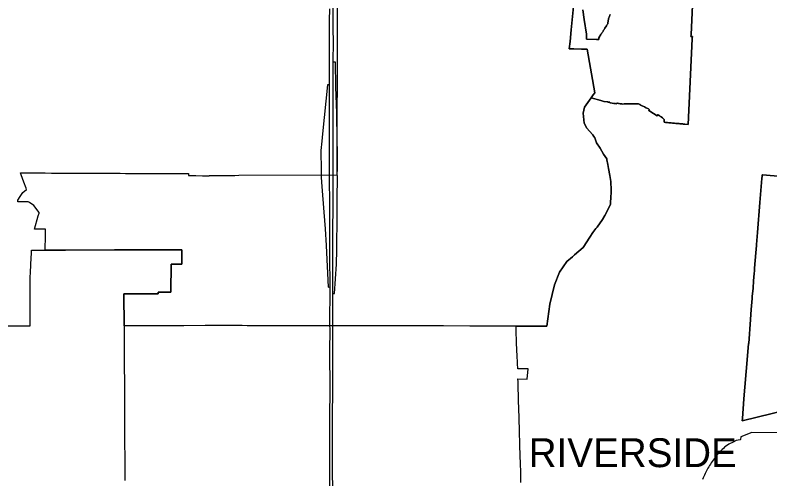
# Model space of a CAD drawing. Extents: x 0 to 34, y 0 to 22.
# Drawn here: x 5.231 to 5.4412, y 15.5644 to 15.6936 of the extents above; entities that cross this region are included whole.
import ezdxf

# ---------------------------------------------------------------- set-up
doc = ezdxf.new("R2010")
doc.units = 0
for name, color, linetype in [('GM_X_Corporation', 7, 'Continuous'), ('GM_X_Corporation_Text', 7, 'Continuous'), ('GM_X_Interchange_Ramps', 7, 'Continuous'), ('GM_X_Interstate_Route', 7, 'Continuous')]:
    doc.layers.add(name, color=color, linetype=linetype)

msp = doc.modelspace()

# ---------------------------------------------------------------- linework, layer by layer
at = {"layer": 'GM_X_Corporation'}
for points in [[(5.38669, 15.69795), (5.38613, 15.69231), (5.38584, 15.68951), (5.38552, 15.68626), (5.38531, 15.68419), (5.38658, 15.68417), (5.38662, 15.68417), (5.38872, 15.68415), (5.38967, 15.68413), (5.39032, 15.68413), (5.3924, 15.67197), (5.39196, 15.67136), (5.39136, 15.67053), (5.38951, 15.66794), (5.38918, 15.66628), (5.38944, 15.66353), (5.38997, 15.6625), (5.39011, 15.66222), (5.39185, 15.66023), (5.39215, 15.65979), (5.3924, 15.65943), (5.39277, 15.65832), (5.39281, 15.65818), (5.39292, 15.65801), (5.39389, 15.65652), (5.3948, 15.65487), (5.39572, 15.65354), (5.39578, 15.65324), (5.39602, 15.65198), (5.39623, 15.65087), (5.3966, 15.64894), (5.39687, 15.64725), (5.39699, 15.64486), (5.39684, 15.64223), (5.39682, 15.64195), (5.39675, 15.64086), (5.39624, 15.63982), (5.39528, 15.63785), (5.39521, 15.63774), (5.39457, 15.63664), (5.39305, 15.63457), (5.39273, 15.63414), (5.3919, 15.633), (5.39099, 15.63177), (5.38917, 15.62886), (5.38678, 15.62679), (5.38618, 15.62627), (5.38467, 15.62497), (5.38261, 15.62195), (5.38121, 15.61847), (5.37994, 15.61307), (5.37908, 15.60694), (5.37819, 15.60694), (5.37797, 15.60694), (5.37758, 15.60694), (5.37715, 15.60694), (5.37697, 15.60695), (5.37468, 15.60695), (5.37461, 15.60695), (5.3742, 15.60695), (5.37215, 15.60695), (5.37047, 15.60695), (5.37006, 15.60695), (5.36442, 15.60696), (5.36409, 15.60696), (5.36375, 15.60696), (5.36347, 15.60696), (5.36334, 15.60696), (5.36305, 15.60696), (5.36272, 15.60697), (5.36039, 15.60698), (5.3603, 15.60698), (5.35998, 15.60698), (5.35764, 15.60699), (5.35032, 15.60702), (5.34996, 15.60702), (5.34984, 15.60703), (5.34662, 15.60703), (5.34509, 15.60703), (5.345, 15.60703), (5.34161, 15.60704), (5.34085, 15.60704), (5.33591, 15.60705), (5.33419, 15.60705), (5.33385, 15.60705), (5.33353, 15.60705), (5.33123, 15.60705), (5.3283, 15.60706), (5.32801, 15.60706), (5.32687, 15.60706), (5.32654, 15.60706), (5.32596, 15.60706), (5.32534, 15.60706), (5.32339, 15.60707), (5.32133, 15.60707), (5.32062, 15.60707), (5.32049, 15.60707), (5.32039, 15.60707), (5.31939, 15.60707), (5.31862, 15.60707), (5.31754, 15.60708), (5.312, 15.60709), (5.31032, 15.60709), (5.30879, 15.60709), (5.30866, 15.60709), (5.308, 15.60709), (5.30621, 15.60708), (5.30559, 15.60708), (5.30476, 15.60708), (5.3043, 15.60708), (5.30115, 15.60706), (5.30111, 15.60706), (5.29839, 15.60708), (5.29802, 15.60708), (5.29787, 15.60709), (5.2976, 15.60709), (5.29737, 15.60709), (5.29561, 15.60709), (5.29421, 15.6071), (5.29231, 15.6071), (5.29135, 15.6071), (5.29035, 15.60711), (5.29032, 15.60711), (5.29012, 15.60711), (5.28775, 15.60711), (5.28743, 15.60711), (5.28621, 15.60712), (5.2859, 15.60712), (5.28569, 15.60712), (5.28553, 15.60712), (5.2855, 15.60712), (5.28504, 15.60712), (5.28394, 15.60712), (5.27803, 15.60709), (5.2775, 15.60709), (5.27749, 15.60709), (5.27546, 15.60708), (5.2745, 15.60708), (5.27355, 15.60708), (5.26139, 15.60706), (5.26139, 15.60713), (5.26138, 15.60812), (5.26137, 15.60919), (5.26136, 15.61032), (5.26133, 15.61258), (5.2613, 15.61548), (5.26129, 15.61584), (5.26129, 15.61593), (5.26828, 15.61593), (5.27083, 15.61593), (5.27083, 15.61597), (5.27084, 15.61642), (5.27442, 15.61642), (5.27442, 15.61648), (5.27449, 15.62421), (5.27449, 15.62422), (5.27709, 15.6242), (5.27741, 15.62419), (5.27743, 15.62537), (5.27743, 15.6254), (5.27745, 15.6282), (5.26348, 15.6282), (5.2617, 15.6282), (5.25869, 15.6282), (5.24508, 15.62813), (5.24355, 15.62813), (5.24329, 15.62813), (5.24205, 15.62813), (5.24181, 15.62813), (5.24084, 15.62813), (5.23942, 15.62813), (5.23943, 15.62943), (5.23946, 15.63087), (5.23946, 15.63174), (5.23945, 15.63398), (5.23792, 15.63398), (5.2364, 15.63398), (5.23749, 15.63771), (5.2377, 15.63843), (5.23776, 15.63863), (5.23626, 15.64056), (5.23502, 15.64137), (5.2347, 15.64158), (5.23463, 15.64158), (5.2325, 15.64159), (5.23192, 15.64159), (5.23181, 15.64159), (5.23181, 15.64192), (5.23181, 15.64208), (5.23244, 15.64305), (5.2332, 15.64421), (5.23421, 15.64502), (5.23407, 15.64542), (5.23346, 15.64708), (5.23271, 15.64914), (5.23253, 15.64963), (5.2336, 15.64964), (5.23364, 15.64964), (5.23373, 15.64964), (5.23569, 15.64963), (5.23697, 15.64963), (5.23795, 15.64962), (5.2394, 15.64962), (5.24114, 15.64961), (5.24299, 15.6496), (5.24352, 15.6496), (5.24555, 15.64959), (5.2471, 15.64958), (5.24795, 15.64958), (5.24864, 15.64958), (5.25018, 15.64957), (5.25174, 15.64956), (5.25254, 15.64956), (5.25407, 15.64955), (5.25527, 15.64955), (5.25562, 15.64955), (5.25716, 15.64954), (5.2587, 15.64953), (5.25901, 15.64953), (5.26025, 15.64953), (5.26179, 15.64952), (5.26333, 15.64951), (5.26366, 15.64951), (5.26488, 15.64951), (5.26642, 15.6495), (5.26796, 15.6495), (5.27194, 15.64948), (5.27827, 15.64945), (5.27929, 15.64943), (5.27928, 15.64888), (5.28062, 15.64888), (5.28136, 15.64888), (5.2832, 15.64887), (5.28506, 15.64886), (5.28506, 15.64895), (5.28585, 15.64895), (5.28744, 15.64895), (5.28903, 15.64896), (5.28951, 15.64896), (5.28988, 15.64896), (5.28991, 15.64896), (5.29073, 15.64896), (5.29158, 15.64896), (5.29221, 15.64896), (5.29328, 15.64897), (5.32068, 15.64911), (5.32068, 15.64931), (5.32068, 15.64951), (5.32076, 15.69174), (5.32069, 15.70479)], [(5.37185, 15.56337), (5.37178, 15.56615), (5.3717, 15.56879), (5.37169, 15.56932), (5.37166, 15.57019), (5.37154, 15.57451), (5.37146, 15.57712), (5.37142, 15.57873), (5.37137, 15.58034), (5.37137, 15.58036), (5.37134, 15.58135), (5.37134, 15.58159), (5.37132, 15.58217), (5.37129, 15.58317), (5.37128, 15.58344), (5.37128, 15.58357), (5.37127, 15.58399), (5.37126, 15.58437), (5.37122, 15.58583), (5.37106, 15.59144), (5.37103, 15.59224), (5.3736, 15.59223), (5.37382, 15.59506), (5.37357, 15.59506), (5.37095, 15.59505), (5.37095, 15.59514), (5.37089, 15.5965), (5.37087, 15.59699), (5.37081, 15.5985), (5.37081, 15.59861), (5.37066, 15.60222), (5.37064, 15.60269), (5.3706, 15.60374), (5.37057, 15.60443), (5.37048, 15.60667), (5.37047, 15.60695), (5.37215, 15.60695), (5.37461, 15.60695), (5.37468, 15.60695), (5.37697, 15.60695), (5.37715, 15.60694), (5.37758, 15.60694), (5.37797, 15.60694), (5.37819, 15.60694), (5.37908, 15.60694), (5.37994, 15.61307), (5.38121, 15.61847), (5.38261, 15.62195), (5.38467, 15.62497), (5.38618, 15.62627), (5.38678, 15.62679), (5.38917, 15.62886), (5.39099, 15.63177), (5.3919, 15.633), (5.39273, 15.63414), (5.39305, 15.63457), (5.39457, 15.63664), (5.39521, 15.63774), (5.39528, 15.63785), (5.39624, 15.63982), (5.39675, 15.64086), (5.39682, 15.64195), (5.39684, 15.64223), (5.39699, 15.64486), (5.39687, 15.64725), (5.3966, 15.64894), (5.39623, 15.65087), (5.39602, 15.65198), (5.39578, 15.65324), (5.39572, 15.65354), (5.3948, 15.65487), (5.39389, 15.65652), (5.39292, 15.65801), (5.39281, 15.65818), (5.39277, 15.65832), (5.3924, 15.65943), (5.39215, 15.65979), (5.39185, 15.66023), (5.39011, 15.66222), (5.38997, 15.6625), (5.38944, 15.66353), (5.38918, 15.66628), (5.38951, 15.66794), (5.39136, 15.67053), (5.39407, 15.6698), (5.3949, 15.66957), (5.39506, 15.66953), (5.39588, 15.66941), (5.39607, 15.66939), (5.39612, 15.66938), (5.39631, 15.66936), (5.39643, 15.66934), (5.3966, 15.66932), (5.39658, 15.66916), (5.39665, 15.66915), (5.39678, 15.66913), (5.39725, 15.66906), (5.39773, 15.669), (5.39821, 15.66893), (5.39849, 15.6689), (5.39851, 15.66905), (5.3987, 15.66903), (5.39899, 15.66899), (5.39918, 15.66896), (5.39947, 15.66892), (5.39966, 15.6689), (5.39994, 15.66886), (5.40013, 15.66883), (5.40055, 15.66884), (5.40074, 15.66885), (5.40103, 15.66885), (5.40122, 15.66886), (5.40152, 15.66886), (5.4017, 15.66887), (5.402, 15.66887), (5.40219, 15.66888), (5.40248, 15.66888), (5.40267, 15.66889), (5.40296, 15.66889), (5.40315, 15.6689), (5.40344, 15.6689), (5.40363, 15.66891), (5.40393, 15.66891), (5.40411, 15.66892), (5.40438, 15.66892), (5.40446, 15.66892), (5.40456, 15.66887), (5.40479, 15.66875), (5.40494, 15.66867), (5.40522, 15.66853), (5.40537, 15.66845), (5.40564, 15.66831), (5.4058, 15.66823), (5.40607, 15.66809), (5.40622, 15.66801), (5.4065, 15.66787), (5.40665, 15.66779), (5.40672, 15.66776), (5.40687, 15.66768), (5.40714, 15.66754), (5.40734, 15.66744), (5.40757, 15.66731), (5.40742, 15.66703), (5.40878, 15.6662), (5.40982, 15.66556), (5.41007, 15.66587), (5.4101, 15.66585), (5.41045, 15.66557), (5.41048, 15.66555), (5.41083, 15.66528), (5.41086, 15.66525), (5.41124, 15.66495), (5.41154, 15.66472), (5.41176, 15.66455), (5.41176, 15.66452), (5.41172, 15.66374), (5.4121, 15.66371), (5.4122, 15.6637), (5.41258, 15.66366), (5.41268, 15.66365), (5.41306, 15.66362), (5.41316, 15.66361), (5.41354, 15.66358), (5.41364, 15.66357), (5.41402, 15.66353), (5.41412, 15.66352), (5.4145, 15.66349), (5.4146, 15.66348), (5.41498, 15.66344), (5.41508, 15.66343), (5.41546, 15.6634), (5.41556, 15.66339), (5.41594, 15.66336), (5.41605, 15.66335), (5.41642, 15.66331), (5.41653, 15.6633), (5.4169, 15.66327), (5.41701, 15.66326), (5.41746, 15.66322), (5.41749, 15.66321), (5.41842, 15.66313), (5.41955, 15.68699), (5.41956, 15.68706), (5.41956, 15.68715), (5.41958, 15.68763), (5.41917, 15.68767), (5.41917, 15.68767), (5.4192, 15.68816), (5.4197, 15.69842)], [(5.4197, 15.69842), (5.4192, 15.68816), (5.41917, 15.68767), (5.41917, 15.68767), (5.41958, 15.68763), (5.41956, 15.68715), (5.41956, 15.68706), (5.41955, 15.68699), (5.41842, 15.66313), (5.41749, 15.66321), (5.41746, 15.66322), (5.41701, 15.66326), (5.4169, 15.66327), (5.41653, 15.6633), (5.41642, 15.66331), (5.41605, 15.66335), (5.41594, 15.66336), (5.41556, 15.66339), (5.41546, 15.6634), (5.41508, 15.66343), (5.41498, 15.66344), (5.4146, 15.66348), (5.4145, 15.66349), (5.41412, 15.66352), (5.41402, 15.66353), (5.41364, 15.66357), (5.41354, 15.66358), (5.41316, 15.66361), (5.41306, 15.66362), (5.41268, 15.66365), (5.41258, 15.66366), (5.4122, 15.6637), (5.4121, 15.66371), (5.41172, 15.66374), (5.41176, 15.66452), (5.41176, 15.66455), (5.41154, 15.66472), (5.41124, 15.66495), (5.41086, 15.66525), (5.41083, 15.66528), (5.41048, 15.66555), (5.41045, 15.66557), (5.4101, 15.66585), (5.41007, 15.66587), (5.40982, 15.66556), (5.40878, 15.6662), (5.40742, 15.66703), (5.40757, 15.66731), (5.40734, 15.66744), (5.40714, 15.66754), (5.40687, 15.66768), (5.40672, 15.66776), (5.40665, 15.66779), (5.4065, 15.66787), (5.40622, 15.66801), (5.40607, 15.66809), (5.4058, 15.66823), (5.40564, 15.66831), (5.40537, 15.66845), (5.40522, 15.66853), (5.40494, 15.66867), (5.40479, 15.66875), (5.40456, 15.66887), (5.40446, 15.66892), (5.40438, 15.66892), (5.40411, 15.66892), (5.40393, 15.66891), (5.40363, 15.66891), (5.40344, 15.6689), (5.40315, 15.6689), (5.40296, 15.66889), (5.40267, 15.66889), (5.40248, 15.66888), (5.40219, 15.66888), (5.402, 15.66887), (5.4017, 15.66887), (5.40152, 15.66886), (5.40122, 15.66886), (5.40103, 15.66885), (5.40074, 15.66885), (5.40055, 15.66884), (5.40013, 15.66883), (5.39994, 15.66886), (5.39966, 15.6689), (5.39947, 15.66892), (5.39918, 15.66896), (5.39899, 15.66899), (5.3987, 15.66903), (5.39851, 15.66905), (5.39849, 15.6689), (5.39821, 15.66893), (5.39773, 15.669), (5.39725, 15.66906), (5.39678, 15.66913), (5.39665, 15.66915), (5.39658, 15.66916), (5.3966, 15.66932), (5.39643, 15.66934), (5.39631, 15.66936), (5.39612, 15.66938), (5.39607, 15.66939), (5.39588, 15.66941), (5.39506, 15.66953), (5.3949, 15.66957), (5.39407, 15.6698), (5.39136, 15.67053), (5.39196, 15.67136), (5.3924, 15.67197), (5.39032, 15.68413), (5.38967, 15.68413), (5.38872, 15.68415), (5.38662, 15.68417), (5.38658, 15.68417), (5.38531, 15.68419), (5.38552, 15.68626), (5.38584, 15.68951), (5.38613, 15.69231), (5.38669, 15.69795)], [(5.38907, 15.69508), (5.38944, 15.69233), (5.39008, 15.68827), (5.39015, 15.68692), (5.39287, 15.68681), (5.3932, 15.68679), (5.39325, 15.68679), (5.39342, 15.68679), (5.39355, 15.68678), (5.39353, 15.68703), (5.39352, 15.68716), (5.39351, 15.68724), (5.39383, 15.68774), (5.3939, 15.68785), (5.39395, 15.68792), (5.39409, 15.68815), (5.3942, 15.68833), (5.39435, 15.68856), (5.39446, 15.68873), (5.39461, 15.68897), (5.39472, 15.68914), (5.39487, 15.68937), (5.39498, 15.68955), (5.39513, 15.68978), (5.39524, 15.68996), (5.39539, 15.69019), (5.3955, 15.69037), (5.39564, 15.69059), (5.39576, 15.69078), (5.3959, 15.691), (5.396, 15.69115), (5.396, 15.69118), (5.39607, 15.69155), (5.39611, 15.6918), (5.39615, 15.69205), (5.3962, 15.69233), (5.39623, 15.69254), (5.39628, 15.69281), (5.3963, 15.69285), (5.39637, 15.69301), (5.39651, 15.6933), (5.39658, 15.69345), (5.39671, 15.69373)], [(5.39671, 15.69373), (5.39658, 15.69345), (5.39651, 15.6933), (5.39637, 15.69301), (5.3963, 15.69285), (5.39628, 15.69281), (5.39623, 15.69254), (5.3962, 15.69233), (5.39615, 15.69205), (5.39611, 15.6918), (5.39607, 15.69155), (5.396, 15.69118), (5.396, 15.69115), (5.3959, 15.691), (5.39576, 15.69078), (5.39564, 15.69059), (5.3955, 15.69037), (5.39539, 15.69019), (5.39524, 15.68996), (5.39513, 15.68978), (5.39498, 15.68955), (5.39487, 15.68937), (5.39472, 15.68914), (5.39461, 15.68897), (5.39446, 15.68873), (5.39435, 15.68856), (5.3942, 15.68833), (5.39409, 15.68815), (5.39395, 15.68792), (5.3939, 15.68785), (5.39383, 15.68774), (5.39351, 15.68724), (5.39352, 15.68716), (5.39353, 15.68703), (5.39355, 15.68678), (5.39342, 15.68679), (5.39325, 15.68679), (5.3932, 15.68679), (5.39287, 15.68681), (5.39015, 15.68692), (5.39008, 15.68827), (5.38944, 15.69233), (5.38944, 15.69235), (5.38907, 15.69508)], [(5.45847, 15.58674), (5.43344, 15.58058), (5.43349, 15.58122), (5.43393, 15.58667), (5.43481, 15.59761), (5.43525, 15.60208), (5.43526, 15.60216), (5.43575, 15.60878), (5.43598, 15.61164), (5.43614, 15.61362), (5.43616, 15.61396), (5.43621, 15.61449), (5.43623, 15.61475), (5.43627, 15.61522), (5.43646, 15.61754), (5.43662, 15.6196), (5.43679, 15.62162), (5.43685, 15.62235), (5.43689, 15.6229), (5.43691, 15.62308), (5.43726, 15.62736), (5.43743, 15.62943), (5.43745, 15.62972), (5.43772, 15.63301), (5.4384, 15.64136), (5.43895, 15.64807), (5.43895, 15.64815), (5.43899, 15.64863), (5.43903, 15.64912), (5.43915, 15.64911), (5.4573, 15.64753)], [(5.4573, 15.64753), (5.43915, 15.64911), (5.43903, 15.64912), (5.43899, 15.64863), (5.43895, 15.64815), (5.43895, 15.64807), (5.4384, 15.64136), (5.43772, 15.63301), (5.43745, 15.62972), (5.43743, 15.62943), (5.43726, 15.62736), (5.43691, 15.62308), (5.43689, 15.6229), (5.43685, 15.62235), (5.43679, 15.62162), (5.43662, 15.6196), (5.43646, 15.61754), (5.43627, 15.61522), (5.43623, 15.61475), (5.43621, 15.61449), (5.4362, 15.61442), (5.43616, 15.61396), (5.43614, 15.61362), (5.43598, 15.61164), (5.43575, 15.60878), (5.43526, 15.60216), (5.43525, 15.60208), (5.43481, 15.59761), (5.43393, 15.58667), (5.43349, 15.58122), (5.43344, 15.58058), (5.45847, 15.58674)], [(5.22535, 15.60707), (5.23181, 15.60705), (5.23188, 15.60705), (5.23406, 15.60704), (5.23523, 15.60704), (5.23523, 15.60722), (5.23523, 15.60768), (5.23523, 15.60936), (5.23523, 15.60955), (5.23523, 15.6096), (5.23523, 15.61088), (5.23523, 15.61119), (5.23523, 15.61265), (5.23523, 15.61386), (5.23523, 15.61426), (5.23523, 15.61483), (5.23523, 15.61571), (5.23523, 15.61579), (5.23523, 15.61676), (5.23523, 15.617), (5.23522, 15.61772), (5.23522, 15.61828), (5.23522, 15.61869), (5.23522, 15.61957), (5.23522, 15.61965), (5.23522, 15.62008), (5.23525, 15.62062), (5.23526, 15.62085), (5.23529, 15.62158), (5.23532, 15.62214), (5.23534, 15.62254), (5.23538, 15.62341), (5.2354, 15.62381), (5.23544, 15.62466), (5.23547, 15.62538), (5.2355, 15.62595), (5.23556, 15.62715), (5.23556, 15.62723), (5.2356, 15.62812), (5.23605, 15.62812), (5.23726, 15.62812), (5.23759, 15.62812), (5.23942, 15.62813), (5.24084, 15.62813), (5.24181, 15.62813), (5.24205, 15.62813), (5.24347, 15.62813), (5.24355, 15.62813), (5.24508, 15.62813), (5.25869, 15.6282), (5.2617, 15.6282), (5.26348, 15.6282), (5.27745, 15.6282), (5.27743, 15.6254), (5.27743, 15.62537), (5.27741, 15.62419), (5.27709, 15.6242), (5.27449, 15.62422), (5.27449, 15.62421), (5.27442, 15.61648), (5.27442, 15.61642), (5.27084, 15.61642), (5.27083, 15.61597), (5.27083, 15.61593), (5.26828, 15.61593), (5.26129, 15.61593), (5.26129, 15.61584), (5.2613, 15.61548), (5.26133, 15.61258), (5.26136, 15.61032), (5.26137, 15.60919), (5.26138, 15.60812), (5.26139, 15.60713), (5.26139, 15.60706), (5.2614, 15.6065), (5.2614, 15.6034), (5.2614, 15.6017), (5.26141, 15.60168), (5.26139, 15.60016), (5.26139, 15.60009), (5.26137, 15.59809), (5.26138, 15.59764), (5.26139, 15.5971), (5.26139, 15.59701), (5.26142, 15.59541), (5.26143, 15.59493), (5.26143, 15.59438), (5.26143, 15.59386), (5.26144, 15.59317), (5.26144, 15.59169), (5.26144, 15.59157), (5.26144, 15.59057), (5.26145, 15.58944), (5.26144, 15.58832), (5.26145, 15.58801), (5.26146, 15.58719), (5.26146, 15.58687), (5.26146, 15.58607), (5.26146, 15.58494), (5.26147, 15.58382), (5.26148, 15.58195), (5.26148, 15.5814), (5.26148, 15.5814), (5.26149, 15.57961), (5.2615, 15.57786), (5.26151, 15.57518), (5.26151, 15.57486), (5.26152, 15.57424), (5.26152, 15.57397), (5.26152, 15.57389), (5.26155, 15.57091), (5.26158, 15.56695), (5.2616, 15.5646), (5.26161, 15.56395)], [(5.44643, 15.57724), (5.43612, 15.57736), (5.43307, 15.57609), (5.43301, 15.57535), (5.43285, 15.57531), (5.4318, 15.57508), (5.43091, 15.57466), (5.42976, 15.57412), (5.42972, 15.5741), (5.42882, 15.57347), (5.42854, 15.57321), (5.42853, 15.57321), (5.42822, 15.57291), (5.4279, 15.5726), (5.4276, 15.57229), (5.4273, 15.57198), (5.427, 15.57165), (5.42671, 15.57133), (5.42643, 15.571), (5.42615, 15.57066), (5.42588, 15.57032), (5.42561, 15.56997), (5.42536, 15.56962), (5.4251, 15.56927), (5.42485, 15.56891), (5.42461, 15.56854), (5.42438, 15.56818), (5.42413, 15.56777), (5.42393, 15.56743), (5.42371, 15.56705), (5.42351, 15.56666), (5.4233, 15.56628), (5.42311, 15.56589), (5.42292, 15.56549), (5.42274, 15.5651), (5.42257, 15.5647), (5.4224, 15.56429)]]:
    msp.add_lwpolyline(points, dxfattribs=at)
at = {"layer": 'GM_X_Interchange_Ramps'}
for p, q in [((5.32067, 15.66114), (5.32064, 15.66386)), ((5.32075, 15.65299), (5.32067, 15.66114)), ((5.31622, 15.64945), (5.31622, 15.64857)), ((5.32071, 15.64228), (5.32074, 15.6485)), ((5.31642, 15.64589), (5.31698, 15.63875)), ((5.32068, 15.63784), (5.32071, 15.64228))]:
    msp.add_line(p, q, dxfattribs=at)
for points in [[(5.32064, 15.66386), (5.32062, 15.66631), (5.32033, 15.67362), (5.3202, 15.68051), (5.3196, 15.68048)], [(5.31853, 15.6742), (5.318, 15.6742), (5.31661, 15.66056), (5.31642, 15.6585)], [(5.31642, 15.6585), (5.31617, 15.6559), (5.31622, 15.65029), (5.31622, 15.64945)], [(5.32071, 15.6494), (5.32077, 15.65046), (5.32075, 15.65299)], [(5.32074, 15.6485), (5.32074, 15.64859), (5.32071, 15.6494)], [(5.31622, 15.64857), (5.31622, 15.64839), (5.31642, 15.64589)], [(5.31698, 15.63875), (5.31735, 15.63402), (5.31761, 15.62939), (5.31814, 15.61786), (5.3187, 15.61789)], [(5.31947, 15.61605), (5.31995, 15.61605), (5.32048, 15.62422), (5.32063, 15.62824), (5.32068, 15.63784)]]:
    msp.add_lwpolyline(points, dxfattribs=at)
at = {"layer": 'GM_X_Interstate_Route'}
for points in [[(5.31962, 15.68302), (5.31963, 15.68369), (5.31961, 15.69218), (5.31965, 15.7001)], [(5.31853, 15.6742), (5.31858, 15.68053), (5.31853, 15.68375), (5.31856, 15.69207), (5.31861, 15.69538)], [(5.31955, 15.64867), (5.31956, 15.64946), (5.31957, 15.65084), (5.31954, 15.65559), (5.31959, 15.66187), (5.31961, 15.66521), (5.31956, 15.6742), (5.3196, 15.68048), (5.31962, 15.68302)], [(5.3187, 15.61789), (5.31865, 15.62662), (5.31865, 15.63308), (5.31865, 15.64074), (5.31852, 15.6484), (5.31853, 15.64949), (5.31855, 15.65084), (5.31852, 15.65559), (5.31856, 15.66187), (5.31859, 15.66521), (5.31853, 15.6742)], [(5.31947, 15.60601), (5.31946, 15.60771), (5.31945, 15.60904), (5.31947, 15.61605), (5.31946, 15.61792), (5.31946, 15.62659), (5.31949, 15.63302), (5.31956, 15.64074), (5.31954, 15.6484), (5.31955, 15.64867)], [(5.31868, 15.55984), (5.31865, 15.56809), (5.31863, 15.57535), (5.31865, 15.58198), (5.3187, 15.5889), (5.31868, 15.60034), (5.31871, 15.60569), (5.31869, 15.60769), (5.31868, 15.60901), (5.31871, 15.61601), (5.3187, 15.61789)], [(5.31945, 15.60012), (5.31945, 15.60037), (5.31947, 15.60568), (5.31947, 15.60601)], [(5.31944, 15.52061), (5.31944, 15.52094), (5.31943, 15.52189), (5.31942, 15.52535), (5.31943, 15.53058), (5.31942, 15.5349), (5.3194, 15.54071), (5.31943, 15.54515), (5.3194, 15.55273), (5.31945, 15.55987), (5.31942, 15.56812), (5.31939, 15.57538), (5.31942, 15.58202), (5.31946, 15.58894), (5.31945, 15.60012)]]:
    msp.add_lwpolyline(points, dxfattribs=at)

# ---------------------------------------------------------------- texts
at = {"layer": 'GM_X_Corporation_Text'}
msp.add_text('RIVERSIDE', height=0.008037, rotation=0, dxfattribs=at).set_placement((5.37402, 15.56769))

doc.saveas('drawing.dxf')
